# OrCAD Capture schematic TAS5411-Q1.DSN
size A
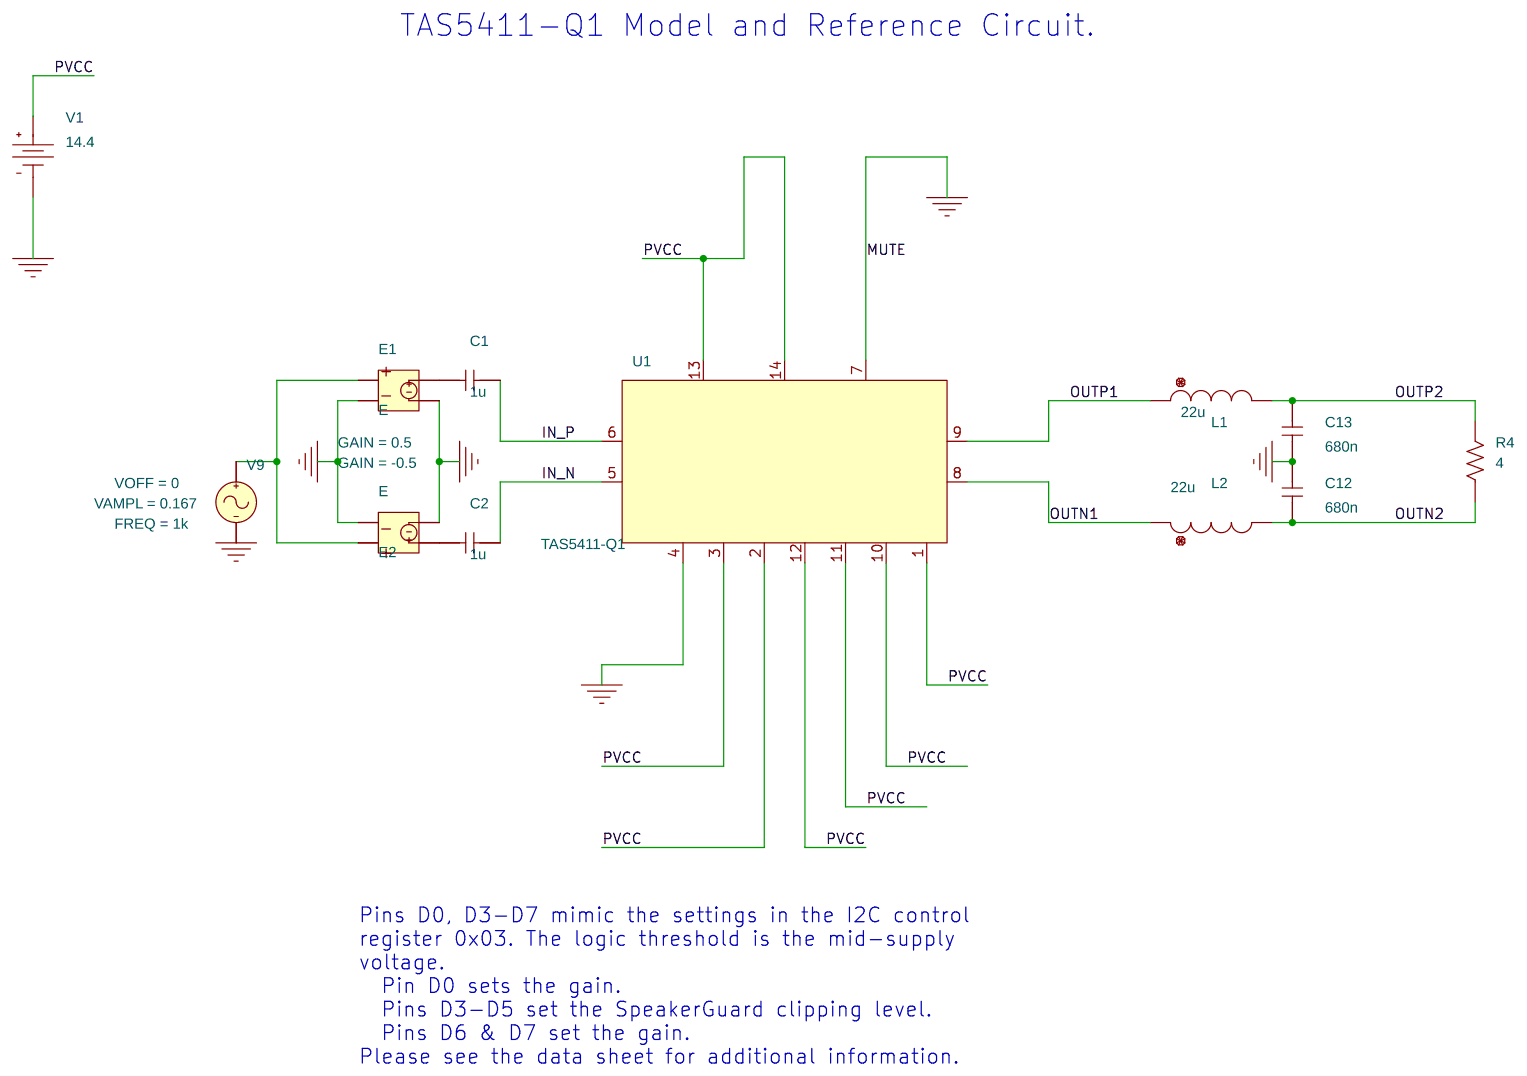
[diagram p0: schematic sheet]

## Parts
C1  1u  [RAD/CK05]
C2  1u  [RAD/CK05]
C12  680n  [RAD/CK05]
C13  680n  [RAD/CK05]
E1  E
E2  E
L1  22u  [DISC/.350x.175/LS.200x.100/.034]
L2  22u  [DISC/.350x.175/LS.200x.100/.034]
R4  4  [AX/RC05]
U1  TAS5411-Q1
V1  VDC
V9  VSIN

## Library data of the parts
C1 C2 C12 C13 = C
E1 = E: GAIN: 0.5
E2 = E: GAIN: -0.5
L1 L2 = L
R4 = R
U1 = TAS5411-Q1_1
V1 = VDC: DC: 14.4
V9 = VSIN: FREQ: 1k; VAMPL: 0.167; VOFF: 0

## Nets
PVCC: U1.1(D0) U1.2(D6) U1.3(D7) U1.10(D3) U1.11(D4) U1.12(D5) U1.13(PVCC) U1.14(SDZ) V1.0(+)
0: C12.2 C13.2 E1.2 E1.4 E2.2 E2.4 U1.4(GND) U1.7(MUTE) V1.1(-) V9.2(-)
IN_N: C2.2 U1.5(IN_N)
IN_P: C1.2 U1.6(IN_P)
OUTN1: L2.1 U1.8(OUTN)
OUTN2: C12.1 L2.2 R4.1
OUTP1: L1.1 U1.9(OUTP)
OUTP2: C13.1 L1.2 R4.2
N115506: E1.1 E2.1 V9.1(+)
N216289: C2.1 E2.3
N216290: C1.1 E1.3

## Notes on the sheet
- TAS5411-Q1 Model and Reference Circuit.
- Pins D0, D3-D7 mimic the settings in the I2C control
  register 0x03. The logic threshold is the mid-supply
  voltage.
    Pin D0 sets the gain.
    Pins D3-D5 set the SpeakerGuard clipping level.
    Pins D6 & D7 set the gain.
  Please see the data sheet for additional information.
